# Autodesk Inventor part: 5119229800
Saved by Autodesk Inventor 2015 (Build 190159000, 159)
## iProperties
Created: 2020-07
Part Number: 5119229800
Checked By: TraceParts S.A.
Material: Generic
Catalog Web Link: www.traceparts.com
Document SubType Name: Modeling
Designer: TraceParts
Density: 1 g/cm^3
Appearance: Default
Company: TraceParts S.A.
Author: TraceParts
REFERENCE: 5119229800
DESIGN: HIB-1000 P 0,37KW (230V 50HZ) - 5119229800
SUPPLIER: Soler & Palau
TraceParts.PartNumber: 10-20122018-119595
TraceParts.PartTitle: HIB-P/HIT-P
TraceParts.InstanceId: 10-20122018-119595EUFQNQU9U39WVOQBCNV2YQJT2
TraceParts.PartStatus: Published
TraceParts.PartVersion: 1.0.2
TRACEPARTS: TRACEPARTS
TraceParts.PartLanguage: en
TraceParts.ClassPath: SOLER_PALAU:10-20122018-119595
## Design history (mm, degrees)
feature "5119229800"
body "Solid1"
